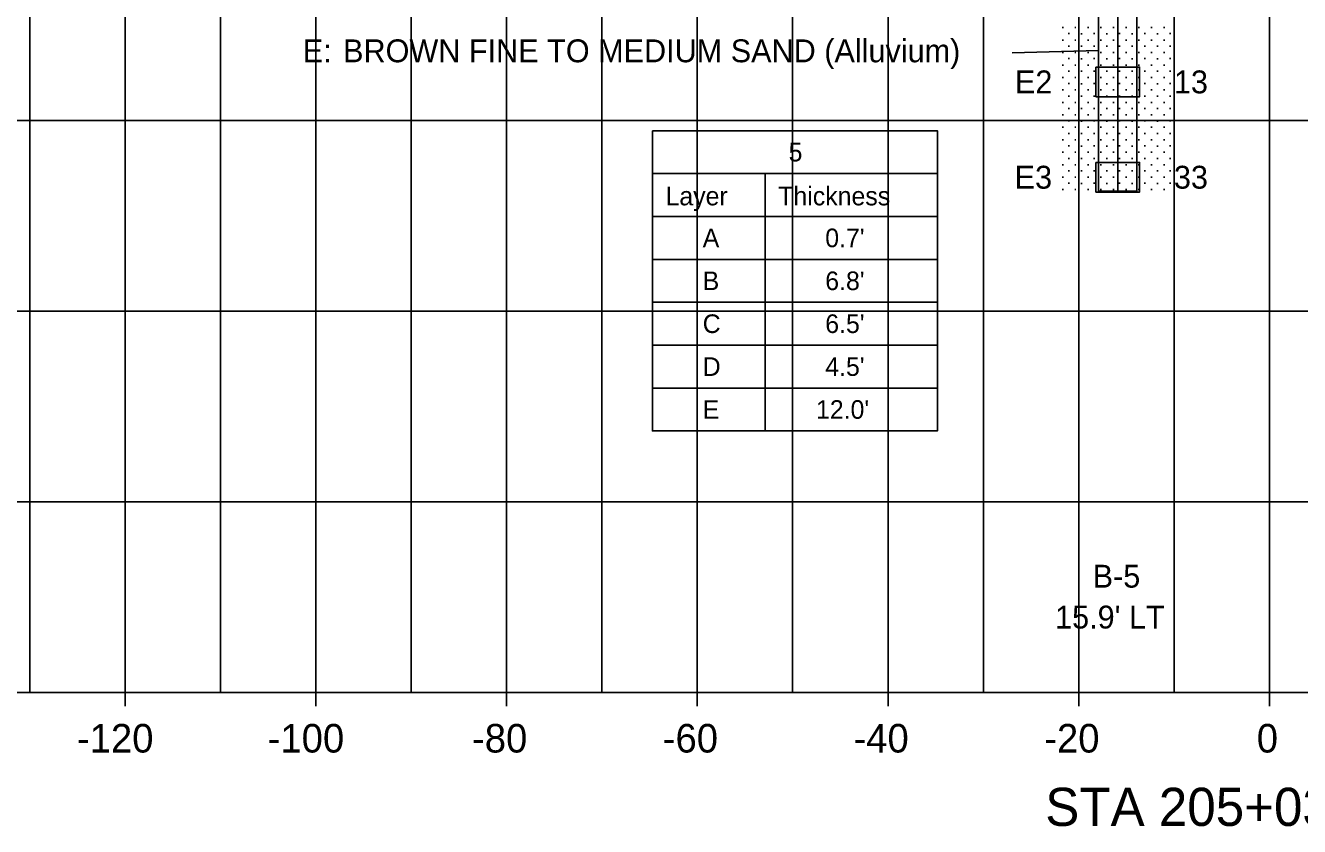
# Model space of a CAD drawing. Extents: x -290 to 297, y 616 to 861.
# Drawn here: x -130.4 to 3.2, y 615.9 to 700 of the extents above; entities that cross this region are included whole.
import ezdxf

# ---------------------------------------------------------------- set-up
doc = ezdxf.new("R2010")
doc.units = 0
for name, color, linetype in [('Cell', 7, 'Continuous'), ('Default', 7, 'Continuous'), ('DisROW Proposed Temp Easements', 7, 'Continuous'), ('Draft_4', 7, 'Continuous'), ('SewerStormPipe', 7, 'Continuous'), ('SheetText', 7, 'Continuous'), ('TextAlignment', 7, 'Continuous'), ('TextAlignmentSml', 7, 'Continuous'), ('V-SWLK-CONC', 7, 'Continuous')]:
    doc.layers.add(name, color=color, linetype=linetype)

msp = doc.modelspace()

# ---------------------------------------------------------------- linework, layer by layer
at = {"layer": 'Default'}
for p, q in [((-15.91, 743.6), (-15.91, 682.6)), ((-13.91, 682.6), (-17.91, 682.6))]:
    msp.add_line(p, q, dxfattribs=at)
at = {"layer": 'DisROW Proposed Temp Easements'}
for p, q in [((-64.7, 684.43), (-34.82, 684.43)), ((-64.7, 657.43), (-64.7, 684.43)), ((-52.88, 684.43), (-52.88, 657.43)), ((-34.82, 684.43), (-34.82, 657.43)), ((-64.7, 679.93), (-34.82, 679.93)), ((-64.7, 675.43), (-34.82, 675.43)), ((-64.7, 670.93), (-34.82, 670.93)), ((-64.7, 666.43), (-34.82, 666.43)), ((-64.7, 661.93), (-34.82, 661.93)), ((-64.7, 657.43), (-34.82, 657.43))]:
    msp.add_line(p, q, dxfattribs=at)
for points in [[(-18.19, 695.6), (-13.62, 695.6), (-13.62, 692.5), (-18.19, 692.5)], [(-18.19, 685.6), (-13.62, 685.6), (-13.62, 682.5), (-18.19, 682.5)]]:
    msp.add_lwpolyline(points, close=True, dxfattribs=at)
at = {"layer": 'Draft_4'}
msp.add_lwpolyline([(-13.91, 706.6), (-17.91, 706.6), (-17.91, 682.6), (-13.91, 682.6)], close=True, dxfattribs=at)
at = {"layer": 'SewerStormPipe'}
for p, q in [((-13.91, 695.6), (-17.91, 695.6)), ((-13.91, 685.6), (-17.91, 685.6))]:
    msp.add_line(p, q, dxfattribs=at)
at = {"layer": 'SheetText'}
msp.add_line((-275.61, 630), (284.21, 630), dxfattribs=at)
at = {"layer": 'TextAlignment'}
for p, q in [((-120, 630), (-120, 787.99)), ((-100, 630), (-100, 787.99)), ((-80, 630), (-80, 787.99)), ((-60, 630), (-60, 787.99)), ((-40, 630), (-40, 787.99)), ((-20, 630), (-20, 787.99)), ((0, 630), (0, 787.99)), ((-275.61, 690), (284.21, 690)), ((-275.61, 650), (284.21, 650)), ((-120, 630), (-120, 628.56)), ((-100, 630), (-100, 628.56)), ((-80, 630), (-80, 628.56)), ((-60, 630), (-60, 628.56)), ((-40, 630), (-40, 628.56)), ((-20, 630), (-20, 628.56)), ((0, 630), (0, 628.56))]:
    msp.add_line(p, q, dxfattribs=at)
at = {"layer": 'TextAlignmentSml'}
for p, q in [((-130, 630), (-130, 787.99)), ((-110, 630), (-110, 787.99)), ((-90, 630), (-90, 787.99)), ((-70, 630), (-70, 787.99)), ((-50, 630), (-50, 787.99)), ((-30, 630), (-30, 787.99)), ((-10, 630), (-10, 787.99)), ((-275.61, 670), (284.21, 670))]:
    msp.add_line(p, q, dxfattribs=at)
at = {"layer": 'V-SWLK-CONC'}
for p, q in [((-21.74, 699.75), (-21.61, 699.75)), ((-21.11, 699.11), (-20.98, 699.11)), ((-20.42, 699.75), (-20.29, 699.75)), ((-19.78, 699.09), (-19.65, 699.09)), ((-19.08, 699.75), (-18.95, 699.75)), ((-18.45, 699.11), (-18.32, 699.11)), ((-17.76, 699.75), (-17.63, 699.75)), ((-17.12, 699.09), (-16.99, 699.09)), ((-16.42, 699.75), (-16.29, 699.75)), ((-15.79, 699.11), (-15.65, 699.11)), ((-15.1, 699.75), (-14.97, 699.75)), ((-14.46, 699.09), (-14.33, 699.09)), ((-13.76, 699.75), (-13.63, 699.75)), ((-13.13, 699.11), (-12.99, 699.11)), ((-12.44, 699.75), (-12.31, 699.75)), ((-11.8, 699.09), (-11.66, 699.09)), ((-11.1, 699.75), (-10.97, 699.75)), ((-10.47, 699.11), (-10.33, 699.11)), ((-17.91, 697.36), (-26.97, 697.11)), ((-21.74, 698.44), (-21.61, 698.44)), ((-21.11, 697.8), (-20.98, 697.8)), ((-20.42, 698.44), (-20.29, 698.44)), ((-19.78, 697.79), (-19.65, 697.79)), ((-19.08, 698.44), (-18.95, 698.44)), ((-18.45, 697.8), (-18.32, 697.8)), ((-17.76, 698.44), (-17.63, 698.44)), ((-17.12, 697.79), (-16.99, 697.79)), ((-16.42, 698.44), (-16.29, 698.44)), ((-15.79, 697.8), (-15.65, 697.8)), ((-15.1, 698.44), (-14.97, 698.44)), ((-14.46, 697.79), (-14.33, 697.79)), ((-13.76, 698.44), (-13.63, 698.44)), ((-13.13, 697.8), (-12.99, 697.8)), ((-12.44, 698.44), (-12.31, 698.44)), ((-11.8, 697.79), (-11.66, 697.79)), ((-11.1, 698.44), (-10.97, 698.44)), ((-10.47, 697.8), (-10.33, 697.8)), ((-21.74, 697.13), (-21.61, 697.13)), ((-21.11, 696.49), (-20.98, 696.49)), ((-20.42, 697.13), (-20.29, 697.13)), ((-19.78, 696.48), (-19.65, 696.48)), ((-19.08, 697.13), (-18.95, 697.13)), ((-18.45, 696.49), (-18.32, 696.49)), ((-17.76, 697.13), (-17.63, 697.13)), ((-17.12, 696.48), (-16.99, 696.48)), ((-16.42, 697.13), (-16.29, 697.13)), ((-15.79, 696.49), (-15.65, 696.49)), ((-15.1, 697.13), (-14.97, 697.13)), ((-14.46, 696.48), (-14.33, 696.48)), ((-13.76, 697.13), (-13.63, 697.13)), ((-13.13, 696.49), (-12.99, 696.49)), ((-12.44, 697.13), (-12.31, 697.13)), ((-11.8, 696.48), (-11.66, 696.48)), ((-11.1, 697.13), (-10.97, 697.13)), ((-10.47, 696.49), (-10.33, 696.49)), ((-21.74, 695.82), (-21.61, 695.82)), ((-21.11, 695.18), (-20.98, 695.18)), ((-20.42, 695.82), (-20.29, 695.82)), ((-19.78, 695.17), (-19.65, 695.17)), ((-19.08, 695.82), (-18.95, 695.82)), ((-18.45, 695.18), (-18.32, 695.18)), ((-17.76, 695.82), (-17.63, 695.82)), ((-17.12, 695.17), (-16.99, 695.17)), ((-16.42, 695.82), (-16.29, 695.82)), ((-15.79, 695.18), (-15.65, 695.18)), ((-15.1, 695.82), (-14.97, 695.82)), ((-14.46, 695.17), (-14.33, 695.17)), ((-13.76, 695.82), (-13.63, 695.82)), ((-13.13, 695.18), (-12.99, 695.18)), ((-12.44, 695.82), (-12.31, 695.82)), ((-11.8, 695.17), (-11.66, 695.17)), ((-11.1, 695.82), (-10.97, 695.82)), ((-10.47, 695.18), (-10.33, 695.18)), ((-21.74, 694.52), (-21.61, 694.52)), ((-21.11, 693.88), (-20.98, 693.88)), ((-20.42, 694.52), (-20.29, 694.52)), ((-19.78, 693.86), (-19.65, 693.86)), ((-19.08, 694.52), (-18.95, 694.52)), ((-18.45, 693.88), (-18.32, 693.88)), ((-17.76, 694.52), (-17.63, 694.52)), ((-17.12, 693.86), (-16.99, 693.86)), ((-16.42, 694.52), (-16.29, 694.52)), ((-15.79, 693.88), (-15.65, 693.88)), ((-15.1, 694.52), (-14.97, 694.52)), ((-14.46, 693.86), (-14.33, 693.86)), ((-13.76, 694.52), (-13.63, 694.52)), ((-13.13, 693.88), (-12.99, 693.88)), ((-12.44, 694.52), (-12.31, 694.52)), ((-11.8, 693.86), (-11.66, 693.86)), ((-11.1, 694.52), (-10.97, 694.52)), ((-10.47, 693.88), (-10.33, 693.88)), ((-21.74, 693.21), (-21.61, 693.21)), ((-21.11, 692.57), (-20.98, 692.57)), ((-20.42, 693.21), (-20.29, 693.21)), ((-19.78, 692.56), (-19.65, 692.56)), ((-19.08, 693.21), (-18.95, 693.21)), ((-18.45, 692.57), (-18.32, 692.57)), ((-17.76, 693.21), (-17.63, 693.21)), ((-17.12, 692.56), (-16.99, 692.56)), ((-16.42, 693.21), (-16.29, 693.21)), ((-15.79, 692.57), (-15.65, 692.57)), ((-15.1, 693.21), (-14.97, 693.21)), ((-14.46, 692.56), (-14.33, 692.56)), ((-13.76, 693.21), (-13.63, 693.21)), ((-13.13, 692.57), (-12.99, 692.57)), ((-12.44, 693.21), (-12.31, 693.21)), ((-11.8, 692.56), (-11.66, 692.56)), ((-11.1, 693.21), (-10.97, 693.21)), ((-10.47, 692.57), (-10.33, 692.57)), ((-21.74, 691.9), (-21.61, 691.9)), ((-21.11, 691.26), (-20.98, 691.26)), ((-20.42, 691.9), (-20.29, 691.9)), ((-19.78, 691.25), (-19.65, 691.25)), ((-19.08, 691.9), (-18.95, 691.9)), ((-18.45, 691.26), (-18.32, 691.26)), ((-17.76, 691.9), (-17.63, 691.9)), ((-17.12, 691.25), (-16.99, 691.25)), ((-16.42, 691.9), (-16.29, 691.9)), ((-15.79, 691.26), (-15.65, 691.26)), ((-15.1, 691.9), (-14.97, 691.9)), ((-14.46, 691.25), (-14.33, 691.25)), ((-13.76, 691.9), (-13.63, 691.9)), ((-13.13, 691.26), (-12.99, 691.26)), ((-12.44, 691.9), (-12.31, 691.9)), ((-11.8, 691.25), (-11.66, 691.25)), ((-11.1, 691.9), (-10.97, 691.9)), ((-10.47, 691.26), (-10.33, 691.26)), ((-21.74, 690.59), (-21.61, 690.59)), ((-21.11, 689.95), (-20.98, 689.95)), ((-20.42, 690.59), (-20.29, 690.59)), ((-19.78, 689.94), (-19.65, 689.94)), ((-19.08, 690.59), (-18.95, 690.59)), ((-18.45, 689.95), (-18.32, 689.95)), ((-17.76, 690.59), (-17.63, 690.59)), ((-17.12, 689.94), (-16.99, 689.94)), ((-16.42, 690.59), (-16.29, 690.59)), ((-15.79, 689.95), (-15.65, 689.95)), ((-15.1, 690.59), (-14.97, 690.59)), ((-14.46, 689.94), (-14.33, 689.94)), ((-13.76, 690.59), (-13.63, 690.59)), ((-13.13, 689.95), (-12.99, 689.95)), ((-12.44, 690.59), (-12.31, 690.59)), ((-11.8, 689.94), (-11.66, 689.94)), ((-11.1, 690.59), (-10.97, 690.59)), ((-10.47, 689.95), (-10.33, 689.95)), ((-21.74, 689.29), (-21.61, 689.29)), ((-21.11, 688.65), (-20.98, 688.65)), ((-20.42, 689.29), (-20.29, 689.29)), ((-19.78, 688.63), (-19.65, 688.63)), ((-19.08, 689.29), (-18.95, 689.29)), ((-18.45, 688.65), (-18.32, 688.65)), ((-17.76, 689.29), (-17.63, 689.29)), ((-17.12, 688.63), (-16.99, 688.63)), ((-16.42, 689.29), (-16.29, 689.29)), ((-15.79, 688.65), (-15.65, 688.65)), ((-15.1, 689.29), (-14.97, 689.29)), ((-14.46, 688.63), (-14.33, 688.63)), ((-13.76, 689.29), (-13.63, 689.29)), ((-13.13, 688.65), (-12.99, 688.65)), ((-12.44, 689.29), (-12.31, 689.29)), ((-11.8, 688.63), (-11.66, 688.63)), ((-11.1, 689.29), (-10.97, 689.29)), ((-10.47, 688.65), (-10.33, 688.65)), ((-21.74, 687.98), (-21.61, 687.98)), ((-21.74, 686.67), (-21.61, 686.67)), ((-21.11, 687.34), (-20.98, 687.34)), ((-20.42, 687.98), (-20.29, 687.98)), ((-20.42, 686.67), (-20.29, 686.67)), ((-19.78, 687.32), (-19.65, 687.32)), ((-19.08, 687.98), (-18.95, 687.98)), ((-19.08, 686.67), (-18.95, 686.67)), ((-18.45, 687.34), (-18.32, 687.34)), ((-17.76, 687.98), (-17.63, 687.98)), ((-17.76, 686.67), (-17.63, 686.67)), ((-17.12, 687.32), (-16.99, 687.32)), ((-16.42, 687.98), (-16.29, 687.98)), ((-16.42, 686.67), (-16.29, 686.67)), ((-15.79, 687.34), (-15.65, 687.34)), ((-15.1, 687.98), (-14.97, 687.98)), ((-15.1, 686.67), (-14.97, 686.67)), ((-14.46, 687.32), (-14.33, 687.32)), ((-13.76, 687.98), (-13.63, 687.98)), ((-13.76, 686.67), (-13.63, 686.67)), ((-13.13, 687.34), (-12.99, 687.34)), ((-12.44, 687.98), (-12.31, 687.98)), ((-12.44, 686.67), (-12.31, 686.67)), ((-11.8, 687.32), (-11.66, 687.32)), ((-11.1, 687.98), (-10.97, 687.98)), ((-11.1, 686.67), (-10.97, 686.67)), ((-10.47, 687.34), (-10.33, 687.34)), ((-21.74, 685.36), (-21.61, 685.36)), ((-21.11, 686.03), (-20.98, 686.03)), ((-20.42, 685.36), (-20.29, 685.36)), ((-19.78, 686.02), (-19.65, 686.02)), ((-19.08, 685.36), (-18.95, 685.36)), ((-18.45, 686.03), (-18.32, 686.03)), ((-17.76, 685.36), (-17.63, 685.36)), ((-17.12, 686.02), (-16.99, 686.02)), ((-16.42, 685.36), (-16.29, 685.36)), ((-15.79, 686.03), (-15.65, 686.03)), ((-15.1, 685.36), (-14.97, 685.36)), ((-14.46, 686.02), (-14.33, 686.02)), ((-13.76, 685.36), (-13.63, 685.36)), ((-13.13, 686.03), (-12.99, 686.03)), ((-12.44, 685.36), (-12.31, 685.36)), ((-11.8, 686.02), (-11.66, 686.02)), ((-11.1, 685.36), (-10.97, 685.36)), ((-10.47, 686.03), (-10.33, 686.03)), ((-21.74, 684.06), (-21.61, 684.06)), ((-21.11, 684.72), (-20.98, 684.72)), ((-20.42, 684.06), (-20.29, 684.06)), ((-19.78, 684.71), (-19.65, 684.71)), ((-19.08, 684.06), (-18.95, 684.06)), ((-18.45, 684.72), (-18.32, 684.72)), ((-17.76, 684.06), (-17.63, 684.06)), ((-17.12, 684.71), (-16.99, 684.71)), ((-16.42, 684.06), (-16.29, 684.06)), ((-15.79, 684.72), (-15.65, 684.72)), ((-15.1, 684.06), (-14.97, 684.06)), ((-14.46, 684.71), (-14.33, 684.71)), ((-13.76, 684.06), (-13.63, 684.06)), ((-13.13, 684.72), (-12.99, 684.72)), ((-12.44, 684.06), (-12.31, 684.06)), ((-11.8, 684.71), (-11.66, 684.71)), ((-11.1, 684.06), (-10.97, 684.06)), ((-10.47, 684.72), (-10.33, 684.72)), ((-21.74, 682.75), (-21.61, 682.75)), ((-21.11, 683.42), (-20.98, 683.42)), ((-20.42, 682.75), (-20.29, 682.75)), ((-19.78, 683.4), (-19.65, 683.4)), ((-19.08, 682.75), (-18.95, 682.75)), ((-18.45, 683.42), (-18.32, 683.42)), ((-17.76, 682.75), (-17.63, 682.75)), ((-17.12, 683.4), (-16.99, 683.4)), ((-16.42, 682.75), (-16.29, 682.75)), ((-15.79, 683.42), (-15.65, 683.42)), ((-15.1, 682.75), (-14.97, 682.75)), ((-14.46, 683.4), (-14.33, 683.4)), ((-13.76, 682.75), (-13.63, 682.75)), ((-13.13, 683.42), (-12.99, 683.42)), ((-12.44, 682.75), (-12.31, 682.75)), ((-11.8, 683.4), (-11.66, 683.4)), ((-11.1, 682.75), (-10.97, 682.75)), ((-10.47, 683.42), (-10.33, 683.42))]:
    msp.add_line(p, q, dxfattribs=at)
for points in [[(-64.7, 688.93), (-34.82, 688.93), (-34.82, 684.43), (-64.7, 684.43)], [(-64.7, 684.43), (-52.88, 684.43), (-52.88, 679.93), (-64.7, 679.93)], [(-52.88, 684.43), (-34.82, 684.43), (-34.82, 679.93), (-52.88, 679.93)], [(-64.7, 679.93), (-52.88, 679.93), (-52.88, 675.43), (-64.7, 675.43)], [(-52.88, 679.93), (-34.82, 679.93), (-34.82, 675.43), (-52.88, 675.43)], [(-64.7, 675.43), (-52.88, 675.43), (-52.88, 670.93), (-64.7, 670.93)], [(-52.88, 675.43), (-34.82, 675.43), (-34.82, 670.93), (-52.88, 670.93)], [(-64.7, 670.93), (-52.88, 670.93), (-52.88, 666.43), (-64.7, 666.43)], [(-52.88, 670.93), (-34.82, 670.93), (-34.82, 666.43), (-52.88, 666.43)], [(-64.7, 666.43), (-52.88, 666.43), (-52.88, 661.93), (-64.7, 661.93)], [(-52.88, 666.43), (-34.82, 666.43), (-34.82, 661.93), (-52.88, 661.93)], [(-64.7, 661.93), (-52.88, 661.93), (-52.88, 657.43), (-64.7, 657.43)], [(-52.88, 661.93), (-34.82, 661.93), (-34.82, 657.43), (-52.88, 657.43)]]:
    msp.add_lwpolyline(points, close=True, dxfattribs=at)

# ---------------------------------------------------------------- texts
at = {"layer": 'Cell'}
for s, height, p in [('-120', 3, (-125.05, 623.7)), ('-100', 3, (-105.05, 623.7)), ('-80', 3, (-83.62, 623.7)), ('-60', 3, (-63.62, 623.7)), ('-40', 3, (-43.62, 623.7)), ('-20', 3, (-23.62, 623.7)), ('0', 3, (-1.33, 623.7)), ('STA 205+03.69', 4.008, (-23.51, 616))]:
    msp.add_text(s, height=height, dxfattribs=at).set_placement(p)
at = {"layer": 'DisROW Proposed Temp Easements'}
for s, p in [('5', (-50.42, 685.71)), ('Layer', (-63.33, 681.1)), ('Thickness', (-51.51, 681.1)), ('A', (-59.43, 676.71)), ("0.7'", (-46.58, 676.71)), ('B', (-59.43, 672.21)), ("6.8'", (-46.58, 672.21)), ('C', (-59.43, 667.71)), ("6.5'", (-46.58, 667.71)), ('D', (-59.43, 663.21)), ("4.5'", (-46.58, 663.21)), ('E', (-59.43, 658.71)), ("12.0'", (-47.55, 658.71))]:
    msp.add_text(s, height=1.95, dxfattribs=at).set_placement(p)
at = {"layer": 'V-SWLK-CONC'}
for s, p in [('E: ', (-101.37, 696.11)), ('BROWN FINE TO MEDIUM SAND (Alluvium)', (-97.14, 696.11)), ('E2', (-26.69, 692.85)), ('13', (-10.02, 692.85)), ('E3', (-26.72, 682.85)), ('33', (-10.02, 682.85)), ('B-5', (-18.54, 641)), ("15.9' LT", (-22.48, 636.71))]:
    msp.add_text(s, height=2.4, dxfattribs=at).set_placement(p)

doc.saveas('drawing.dxf')
